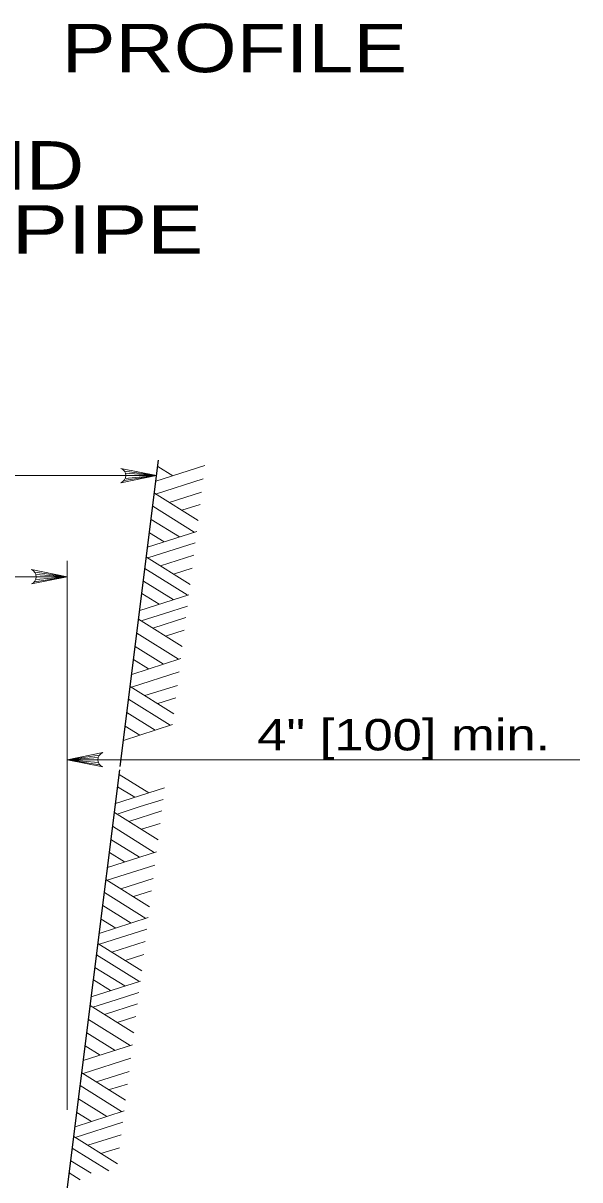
# Model space of a CAD drawing. Extents: x 1083.1 to 1117.1, y 697.4 to 741.4.
# Drawn here: x 1094.7 to 1097.46, y 722.98 to 728.72 of the extents above; entities that cross this region are included whole.
import ezdxf
from ezdxf.enums import TextEntityAlignment as Align

# ---------------------------------------------------------------- set-up
doc = ezdxf.new("R2010")
doc.units = 0
doc.header["$LTSCALE"] = 0.062
doc.layers.add('1', color=7, linetype='Continuous', lineweight=13)

msp = doc.modelspace()

# ---------------------------------------------------------------- linework, layer by layer
at = {"layer": '1', "lineweight": 25}
for p, q in [((1095.17858, 725.03008), (1095.36908, 726.54942)), ((1094.915, 722.92817), (1095.17642, 725.01283))]:
    msp.add_line(p, q, dxfattribs=at)
at = {"layer": '1'}
for p, q in [((1095.19933, 726.49625), (1095.35958, 726.47383)), ((1095.20475, 726.48517), (1095.35958, 726.47383)), ((1095.35608, 726.44583), (1095.59975, 726.52425)), ((1095.36533, 726.5195), (1095.44017, 726.47308)), ((1089.9645, 726.47383), (1095.35958, 726.47383)), ((1095.1975, 726.44908), (1095.35958, 726.47383)), ((1095.20358, 726.45942), (1095.35958, 726.47383)), ((1095.20642, 726.47383), (1095.35958, 726.47383)), ((1095.35467, 726.38208), (1095.5915, 726.45775)), ((1095.34858, 726.38583), (1095.5655, 726.25042)), ((1095.42208, 726.34025), (1095.58308, 726.39133)), ((1095.34058, 726.32217), (1095.54675, 726.19325)), ((1095.48542, 726.30183), (1095.57542, 726.32975)), ((1095.33233, 726.25642), (1095.47317, 726.169)), ((1095.31492, 726.11767), (1095.55867, 726.19683)), ((1095.3155, 726.06458), (1095.55175, 726.14025)), ((1095.32392, 726.18925), (1095.39675, 726.14442)), ((1094.915, 723.32475), (1094.915, 726.05008)), ((1095.30883, 726.06908), (1095.52642, 725.93358)), ((1095.37817, 726.0255), (1095.54383, 726.07808)), ((1090.41717, 725.97142), (1094.915, 725.97142)), ((1094.75283, 725.94667), (1094.915, 725.97142)), ((1094.75475, 725.99383), (1094.915, 725.97142)), ((1094.759, 725.95708), (1094.915, 725.97142)), ((1094.76017, 725.98275), (1094.915, 725.97142)), ((1094.76183, 725.97142), (1094.915, 725.97142)), ((1095.30175, 726.01183), (1095.51183, 725.88092)), ((1095.44358, 725.98467), (1095.53583, 726.01375)), ((1095.29383, 725.94892), (1095.4415, 725.85783)), ((1095.27567, 725.8045), (1095.51933, 725.88217)), ((1095.28617, 725.88817), (1095.37183, 725.83533)), ((1095.39867, 725.78917), (1095.51217, 725.825)), ((1095.27017, 725.76017), (1095.487, 725.62483)), ((1095.28367, 725.752), (1095.39867, 725.78917)), ((1095.3415, 725.71567), (1095.505, 725.76858)), ((1095.26158, 725.69158), (1095.46825, 725.56175)), ((1095.40417, 725.67658), (1095.49717, 725.70558)), ((1095.25325, 725.62575), (1095.394, 725.53767)), ((1095.23583, 725.48708), (1095.47958, 725.5655)), ((1095.24517, 725.56067), (1095.31992, 725.51433)), ((1095.23442, 725.42333), (1095.47125, 725.499)), ((1095.22833, 725.42708), (1095.44525, 725.29167)), ((1095.30183, 725.3815), (1095.46292, 725.43242)), ((1095.22033, 725.36342), (1095.4265, 725.2345)), ((1095.36533, 725.343), (1095.45517, 725.371)), ((1095.21217, 725.29767), (1095.353, 725.21025)), ((1095.19475, 725.15892), (1095.43858, 725.238)), ((1095.20367, 725.23033), (1095.2765, 725.18567)), ((1095.07525, 725.08558), (1094.915, 725.06317)), ((1095.06983, 725.0745), (1094.915, 725.06317)), ((1094.915, 725.06317), (1097.46167, 725.06317)), ((1095.06817, 725.06317), (1094.915, 725.06317)), ((1095.071, 725.04875), (1094.915, 725.06317)), ((1095.07717, 725.03842), (1094.915, 725.06317)), ((1095.17358, 724.99017), (1095.32125, 724.89908)), ((1095.1555, 724.84575), (1095.39908, 724.92342)), ((1095.166, 724.92942), (1095.25158, 724.87658)), ((1095.16342, 724.79325), (1095.27842, 724.83033)), ((1095.27842, 724.83033), (1095.39192, 724.86617)), ((1095.14992, 724.80142), (1095.36683, 724.666)), ((1095.22125, 724.75683), (1095.38475, 724.80975)), ((1095.14133, 724.73275), (1095.348, 724.603)), ((1095.28392, 724.71775), (1095.37692, 724.74683)), ((1095.133, 724.667), (1095.27383, 724.57892)), ((1095.11558, 724.52825), (1095.35942, 724.60675)), ((1095.12492, 724.60192), (1095.19967, 724.55558)), ((1095.11425, 724.46458), (1095.351, 724.54017)), ((1095.18158, 724.42275), (1095.34275, 724.47367)), ((1095.10808, 724.46817), (1095.325, 724.33292)), ((1095.10008, 724.40467), (1095.30625, 724.27558)), ((1095.24508, 724.38425), (1095.335, 724.41225)), ((1095.09192, 724.33892), (1095.23275, 724.25142)), ((1095.0745, 724.20017), (1095.31833, 724.27925)), ((1095.08342, 724.27158), (1095.15633, 724.22692)), ((1095.07517, 724.147), (1095.31125, 724.22275)), ((1095.06842, 724.1515), (1095.286, 724.01608)), ((1095.13767, 724.10792), (1095.30342, 724.16058)), ((1095.06125, 724.09433), (1095.27142, 723.96342)), ((1095.20308, 724.067), (1095.29533, 724.09625)), ((1095.05333, 724.03133), (1095.201, 723.94025)), ((1095.03525, 723.88692), (1095.27883, 723.96458)), ((1095.04575, 723.97058), (1095.13133, 723.91775)), ((1095.15817, 723.87158), (1095.27167, 723.90742)), ((1095.02967, 723.84267), (1095.24658, 723.70725)), ((1095.04317, 723.83433), (1095.15817, 723.87158)), ((1095.10108, 723.79808), (1095.26458, 723.851)), ((1095.16367, 723.759), (1095.25675, 723.788)), ((1095.02108, 723.774), (1095.22775, 723.64425)), ((1095.01283, 723.70825), (1095.15358, 723.62008)), ((1094.9955, 723.5695), (1095.23917, 723.64792)), ((1095.00467, 723.64317), (1095.07942, 723.59667)), ((1094.994, 723.50575), (1095.23075, 723.58142)), ((1094.98792, 723.50942), (1095.20475, 723.374)), ((1095.06133, 723.464), (1095.2225, 723.51492)), ((1094.97992, 723.44583), (1095.186, 723.31683)), ((1095.12483, 723.4255), (1095.21475, 723.45342)), ((1094.97167, 723.38), (1095.1125, 723.29267)), ((1094.95433, 723.24133), (1095.19808, 723.3205)), ((1094.96325, 723.31283), (1095.03608, 723.26808)), ((1094.95492, 723.18825), (1095.191, 723.264)), ((1094.94817, 723.19275), (1095.16575, 723.05725)), ((1095.01758, 723.14917), (1095.18317, 723.20175)), ((1094.941, 723.13558), (1095.1215, 723.02317)), ((1095.08283, 723.10825), (1095.17508, 723.13733)), ((1094.93308, 723.07258), (1095.03408, 723.01033)), ((1094.9255, 723.01183), (1094.98017, 722.97808))]:
    msp.add_line(p, q, dxfattribs=at)
for points in [[(1095.18258, 726.43842), (1095.35958, 726.47383), (1095.18258, 726.50925)], [(1094.738, 725.936), (1094.915, 725.97142), (1094.738, 726.00683)], [(1095.092, 725.02775), (1094.915, 725.06317), (1095.092, 725.09858)]]:
    msp.add_lwpolyline(points, dxfattribs=at)
for centre, start, end in [((1095.1683, 726.47389), 292.08605, 67.91218), ((1094.72371, 725.97148), 292.08605, 67.91218), ((1095.1063, 725.0632), 112.08782, 247.91395)]:
    msp.add_arc(centre, 0.0382, start, end, dxfattribs=at)

# ---------------------------------------------------------------- texts
at = {"layer": '1', "width": 1.25}
msp.add_text('PROFILE', height=0.24, dxfattribs=at).set_placement((1094.88783, 728.47608))
at = {"layer": '1'}
for s, height, width, p in [('EROSION CONTROL PAD AND', 0.24, 1.25, (1092.09096, 727.89375)), ('ANIMAL GUARD FOR OUTLET PIPE', 0.24, 1.3, (1092.09096, 727.57575)), ('4" [100] min.', 0.156, 1.25, (1096.58713, 725.10925))]:
    msp.add_text(s, height=height, dxfattribs=dict(at, width=width)).set_placement(p, align=Align.CENTER)

doc.saveas('drawing.dxf')
